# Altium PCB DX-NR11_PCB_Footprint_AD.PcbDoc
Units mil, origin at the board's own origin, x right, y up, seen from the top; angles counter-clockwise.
Board outline 6000 x 4000 mil, 2 copper layers (Top Layer, Bottom Layer); 1 components, 0 nets, 18 pads, 0 vias.
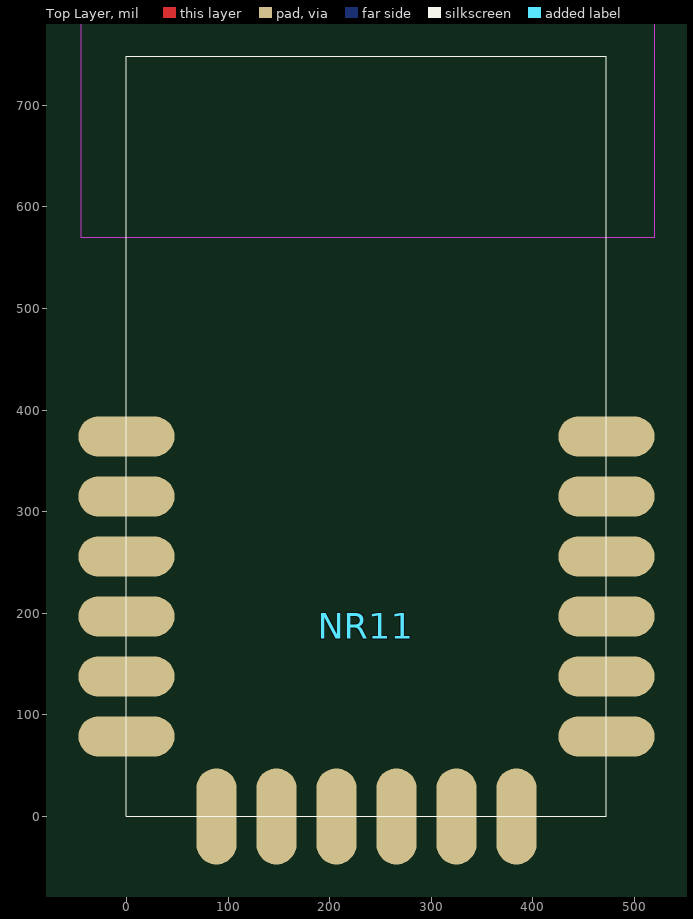
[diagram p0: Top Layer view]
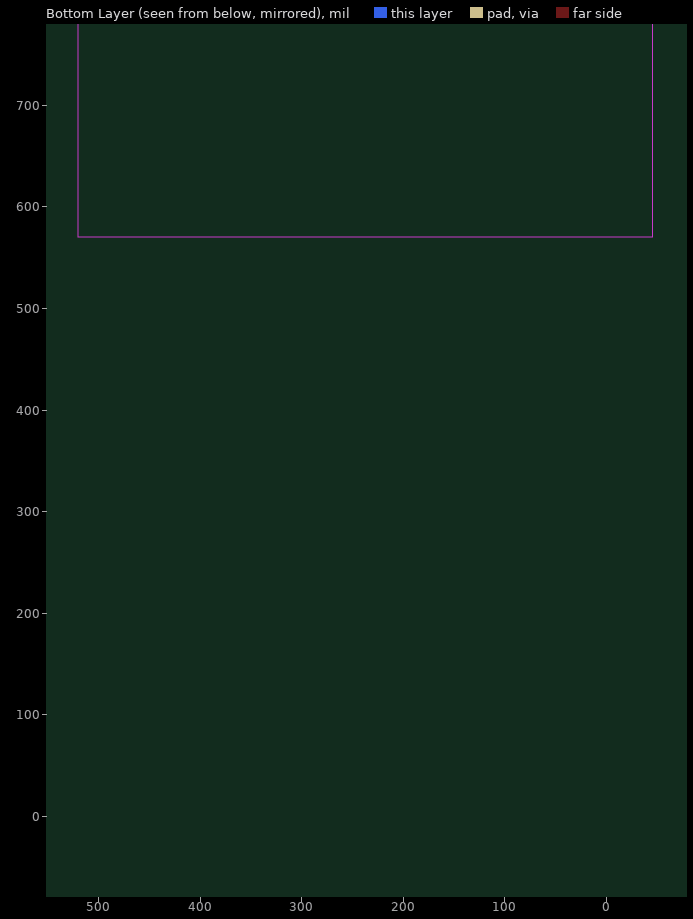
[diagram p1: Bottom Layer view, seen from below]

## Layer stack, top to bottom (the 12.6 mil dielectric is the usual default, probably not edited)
Top Solder: solder mask 0.4, Solder Resist, Dk 3.5
Top Layer: signal copper 1.4
Dielectric 1: dielectric 12.6, FR-4, Dk 4.8
Bottom Layer: signal copper 1.4
Bottom Solder: solder mask 0.4, Solder Resist, Dk 3.5

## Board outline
-2649.16,-1510.52 3350.84,-1510.52 3350.84,2489.48 -2649.16,2489.48

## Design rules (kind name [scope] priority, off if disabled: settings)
Clearance [All] p1: gap=10 ignorepadtopadclearanceinfootprint=FALSE except(0: Arc-Hole Track-Hole SMDPad-Hole THPad-Hole Via-Hole Fill-Hole Poly-Hole Region-Hole Text-Hole)
PolygonConnect [All] p1: connectstyle=Relief reliefconductorwidth=10 reliefentries=4 polygonreliefangle="90 Angle" airgapwidth=10
RoutingVias [All] p1: holewidth=28 width=50 viastyle="Through Hole" minholewidth=28 minwidth=50 maxholewidth=28 maxwidth=50
SolderMaskExpansion [All] p1: expansion=4 istentingtop=FALSE
Width [All] p1: maxlimit=10 minlimit=10 preferedwidth=10
30 further rules are at their usual default settings.

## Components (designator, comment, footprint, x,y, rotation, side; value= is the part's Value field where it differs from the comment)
NR11 "" NR11 0,0 r0 top

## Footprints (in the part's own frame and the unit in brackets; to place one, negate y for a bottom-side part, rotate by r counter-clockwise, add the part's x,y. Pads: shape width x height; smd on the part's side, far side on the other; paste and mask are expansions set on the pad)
NR11 [mm]
  oval 2.4x1 smd paste-2539.97 mask-2539.97: 1(0,9.5)
  oval 2.4x1 smd mask-2539.97: 2(0,8) 3(0,6.5) 4(0,5) 5(0,3.5) 6(0,2) 13(12,2) 14(12,3.5) 15(12,5) 16(12,6.5) 17(12,8) 18(12,9.5)
  oval 1x2.4 smd mask-2539.97: 7(2.25,0) 8(3.75,0) 9(5.25,0) 10(6.75,0) 11(8.25,0) 12(9.75,0)
  Keep-Out Layer region: -1.143,14.478 13.208,14.478 13.208,20.193 -1.143,20.193
  silkscreen extent 0,0 12,19

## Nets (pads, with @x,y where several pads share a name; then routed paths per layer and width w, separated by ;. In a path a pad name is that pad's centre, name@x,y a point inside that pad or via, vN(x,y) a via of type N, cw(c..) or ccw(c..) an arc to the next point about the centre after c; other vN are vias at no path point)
pads on no net: NR11.1 NR11.2 NR11.3 NR11.4 NR11.5 NR11.6 NR11.7 NR11.8 NR11.9 NR11.10 NR11.11 NR11.12 NR11.13 NR11.14 NR11.15 NR11.16 NR11.17 NR11.18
